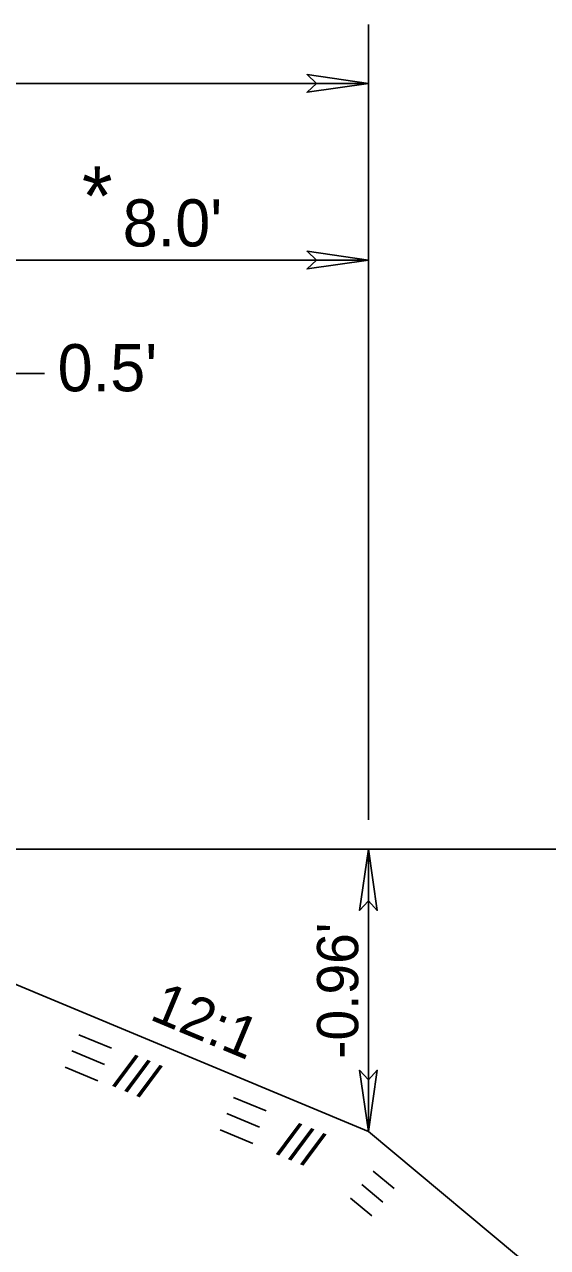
# Model space of a CAD drawing. Extents: x 6561 to 6787, y 19927 to 20919.
# Drawn here: x 6717.22 to 6726.1, y 20861.89 to 20882.65 of the extents above; entities that cross this region are included whole.
import ezdxf

# ---------------------------------------------------------------- set-up
doc = ezdxf.new("R2010")
doc.units = 0
doc.layers.add('Level 1', color=7, linetype='Continuous')
doc.layers.add('Level 7', color=7, linetype='Continuous')

msp = doc.modelspace()

# ---------------------------------------------------------------- linework, layer by layer
at = {"layer": 'Level 1'}
for p, q in [((6723.057, 20882.65), (6723.057, 20869.15)), ((6701.247, 20881.65), (6723.057, 20881.65)), ((6715.107, 20878.65), (6723.057, 20878.65)), ((6715.557, 20876.726), (6717.557, 20876.726)), ((6779.047, 20868.65), (6628.473, 20868.65)), ((6723.057, 20863.858), (6723.057, 20868.65))]:
    msp.add_line(p, q, dxfattribs=at)
for points in [[(6723.057, 20881.65), (6722.018, 20881.8), (6722.178, 20881.65), (6722.018, 20881.5)], [(6723.057, 20878.65), (6722.018, 20878.8), (6722.178, 20878.65), (6722.018, 20878.5)], [(6723.057, 20868.65), (6722.907, 20867.611), (6723.057, 20867.771), (6723.207, 20867.611)], [(6723.057, 20863.858), (6723.207, 20864.897), (6723.057, 20864.737), (6722.907, 20864.897)]]:
    msp.add_lwpolyline(points, close=True, dxfattribs=at)
at = {"layer": 'Level 7'}
for p, q in [((6715.057, 20867.192), (6723.057, 20863.858)), ((6723.057, 20863.858), (6733.557, 20855.108))]:
    msp.add_line(p, q, dxfattribs=at)
for points in [[(6718.14, 20865.501), (6718.694, 20865.271)], [(6718.025, 20865.225), (6718.579, 20864.994)], [(6717.91, 20864.948), (6718.464, 20864.717)], [(6720.769, 20864.437), (6721.323, 20864.207)], [(6720.654, 20864.161), (6721.208, 20863.93)], [(6720.539, 20863.884), (6721.093, 20863.654)], [(6723.139, 20863.187), (6723.497, 20862.888)], [(6722.947, 20862.957), (6723.305, 20862.658)], [(6722.755, 20862.727), (6723.113, 20862.428)]]:
    msp.add_lwpolyline(points, dxfattribs=at)

# ---------------------------------------------------------------- texts
at = {"layer": 'Level 1'}
for s, height, p in [('*', 1, (6718.194, 20879.239)), ("8.0'", 0.8, (6718.886, 20878.881)), ("0.5'", 0.8, (6717.782, 20876.423))]:
    msp.add_text(s, height=height, dxfattribs=at).set_placement(p)
for s, rotation, p in [("-0.96'", 90, (6722.885, 20865.091)), ('12:1', 337.3801, (6719.322, 20865.768))]:
    msp.add_text(s, height=0.7, rotation=rotation, dxfattribs=at).set_placement(p)
at = {"layer": 'Level 7'}
for p in [(6718.709, 20864.64), (6721.488, 20863.482)]:
    msp.add_text('///', height=0.6, rotation=337.3802, dxfattribs=at).set_placement(p)

doc.saveas('drawing.dxf')
